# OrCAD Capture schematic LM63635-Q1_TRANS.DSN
size D; title: LM63635-Q1 3.5-V to 36-V, 3.25-A, Automotive Step-down; note: Datasheet: SNVSBK9C      EVM: SNVU617; note: Step-Down Converter.
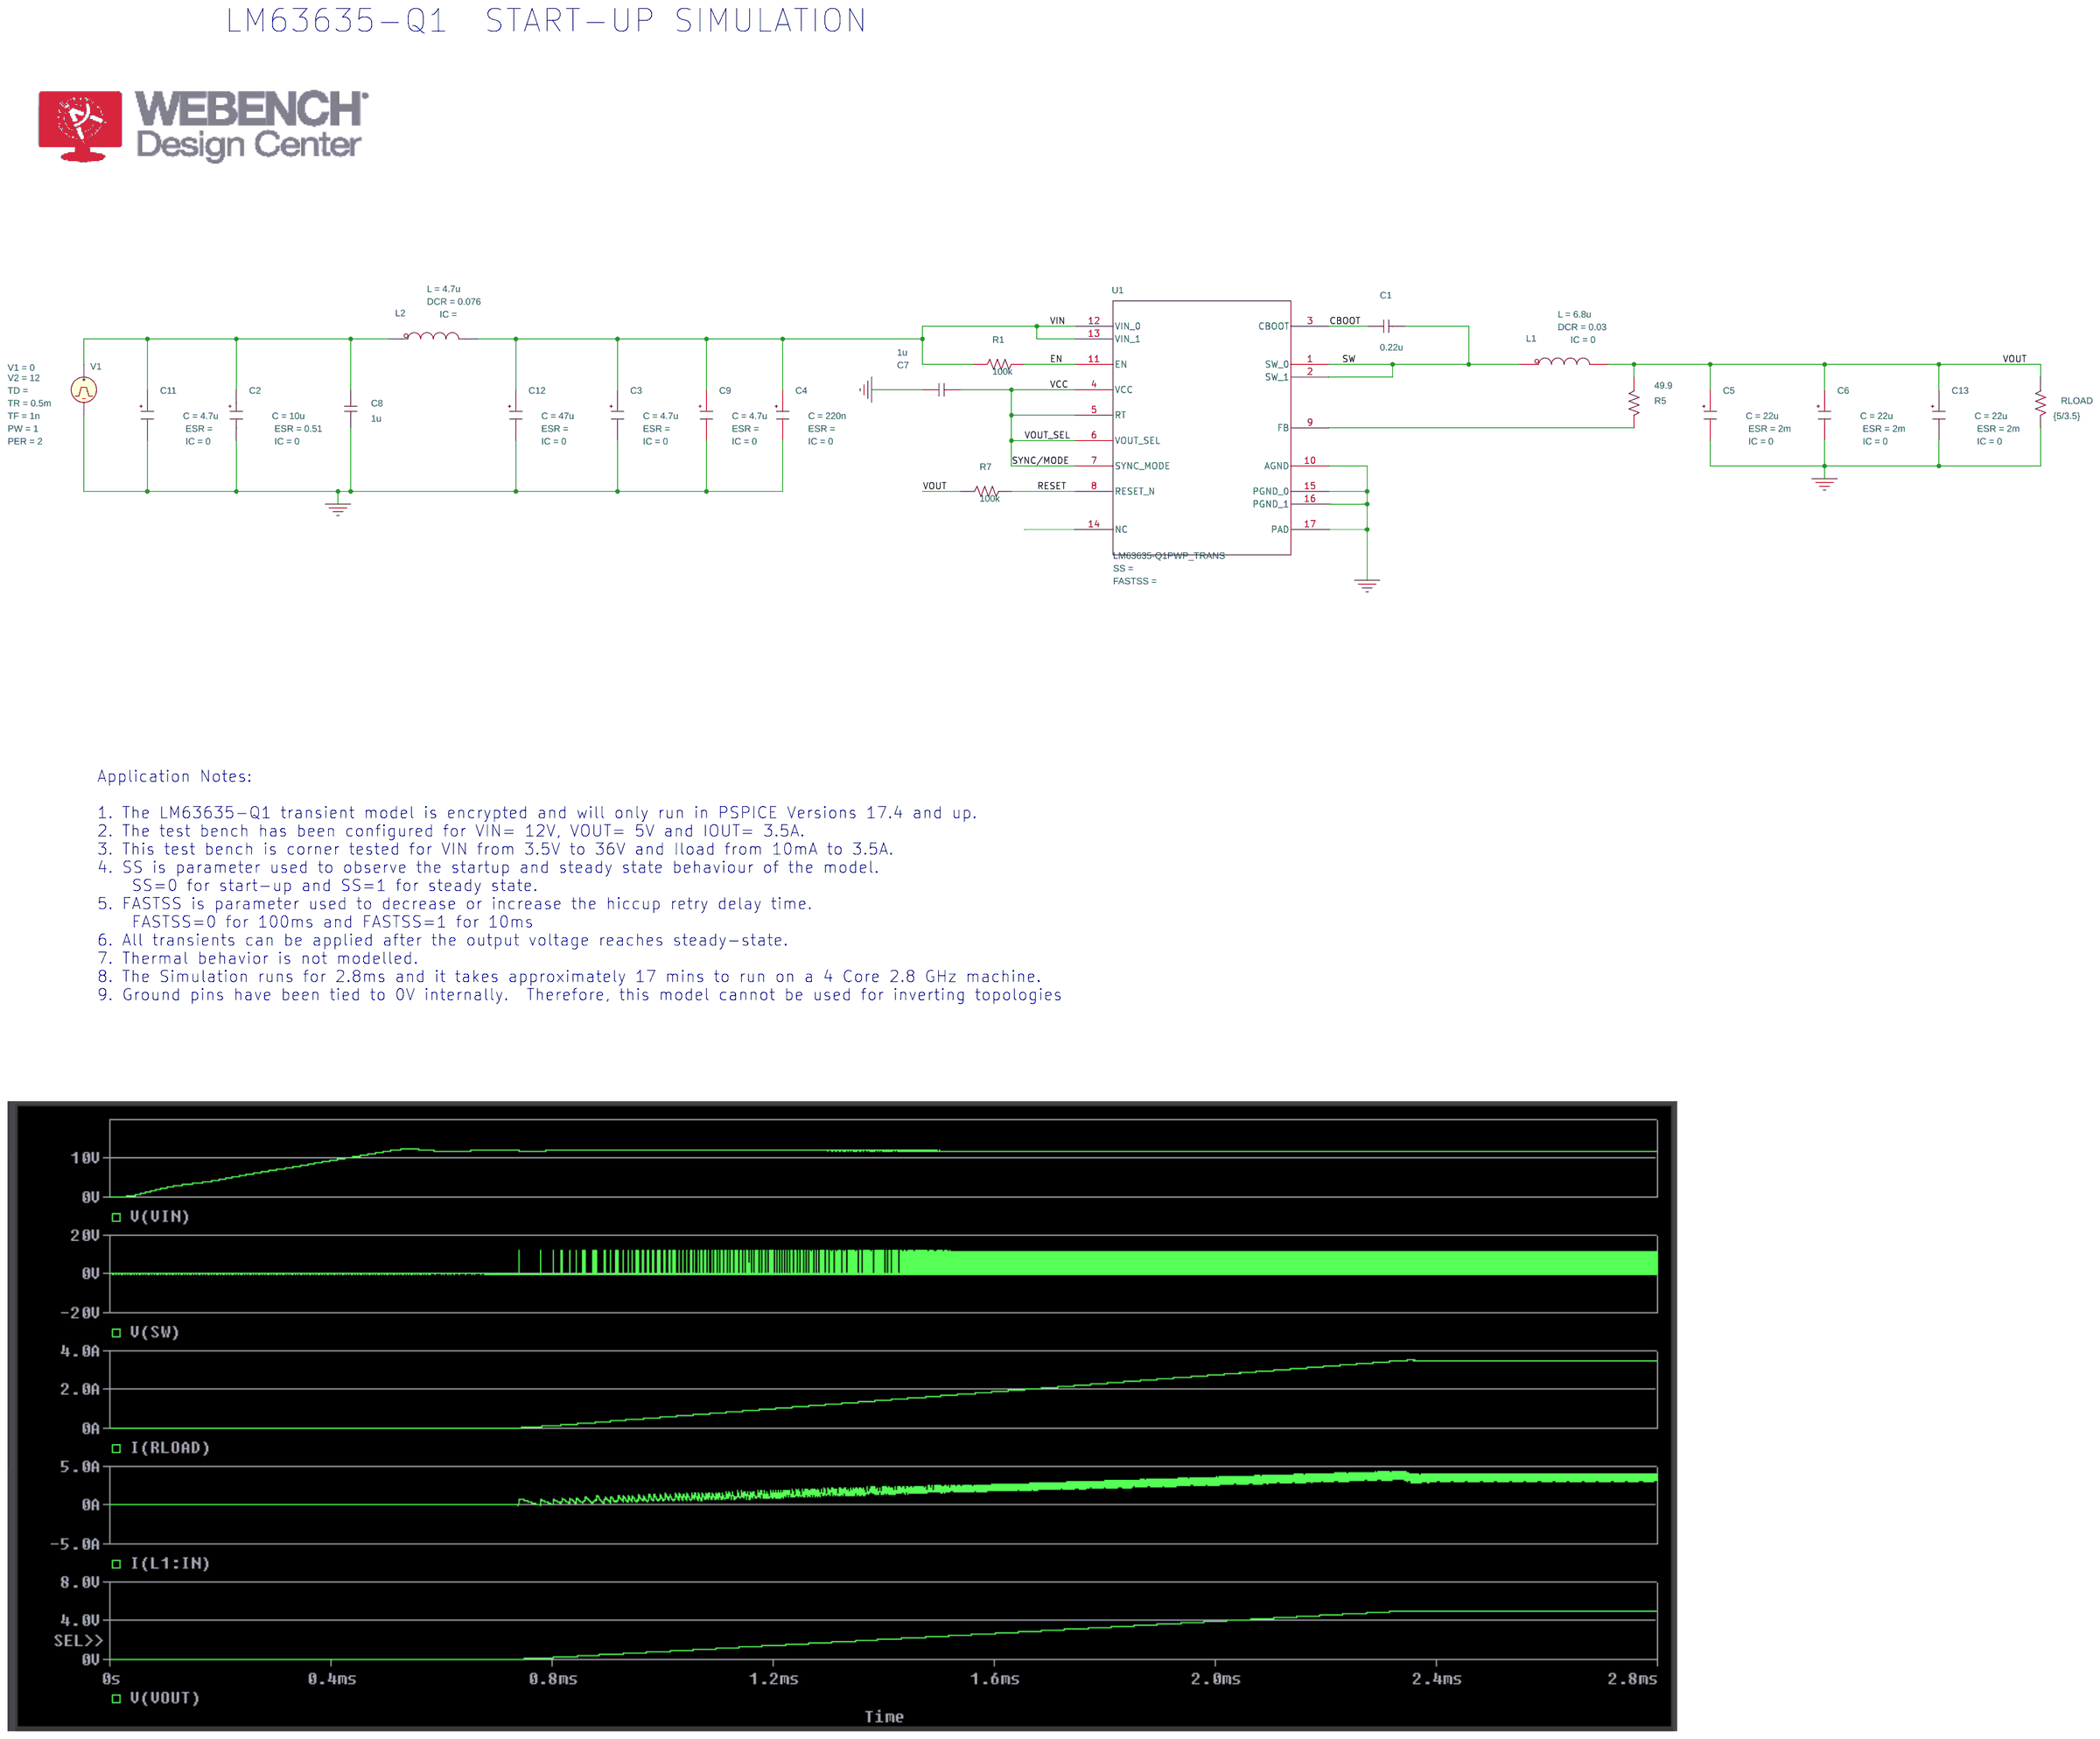
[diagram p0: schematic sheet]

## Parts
C1  0.22u  [RAD/CK05]
C2  CESR
C3  CESR
C4  CESR
C5  CESR
C6  CESR
C7  1u  [RAD/CK05]
C8  1u  [RAD/CK05]
C9  CESR
C11  CESR
C12  CESR
C13  CESR
L1  LDCR
L2  LDCR
R1  100k  [AX/RC05]
R5  49.9  [AX/RC05]
R7  100k  [AX/RC05]
RLOAD  {5/3.5}  [AX/RC05]
U1  LM63635-Q1PWP_TRANS  [PWP0016K_N]
V1  VPULSE

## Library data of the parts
C1 C7 C8 = C: IC: 0
C2 = CESR_0: C: 10u; ESR: 0.51; IC: 0; PSpiceTemplate: X^@REFDES %IN %OUT @MODEL PARAMS:  ?C|C=@C||C=100u|  ?ESR|ESR=@ESR||ESR=0.01| ?X|X=@X||X=2|  ?IC|IC=@IC||IC=2|; X: 1
C3 C9 = CESR_0: C: 4.7u; IC: 0; PSpiceTemplate: X^@REFDES %IN %OUT @MODEL PARAMS:  ?C|C=@C||C=100u|  ?ESR|ESR=@ESR||ESR=0.01| ?X|X=@X||X=2|  ?IC|IC=@IC||IC=2|; X: 2
C4 = CESR_0: C: 220n; IC: 0; PSpiceTemplate: X^@REFDES %IN %OUT @MODEL PARAMS:  ?C|C=@C||C=100u|  ?ESR|ESR=@ESR||ESR=0.01| ?X|X=@X||X=2|  ?IC|IC=@IC||IC=2|; X: 2
C5 = CESR_0: C: 22u; ESR: 2m; IC: 0; PSpiceTemplate: X^@REFDES %IN %OUT @MODEL PARAMS:  ?C|C=@C||C=100u|  ?ESR|ESR=@ESR||ESR=0.01| ?X|X=@X||X=2|  ?IC|IC=@IC||IC=2|; X: 1
C6 C13 = CESR_0: C: 22u; ESR: 2m; IC: 0; PSpiceTemplate: X^@REFDES %IN %OUT @MODEL PARAMS:  ?C|C=@C||C=100u|  ?ESR|ESR=@ESR||ESR=0.01| ?X|X=@X||X=2|  ?IC|IC=@IC||IC=2|; X: 2
C11 = CESR_0: C: 4.7u; IC: 0; PSpiceTemplate: X^@REFDES %IN %OUT @MODEL PARAMS:  ?C|C=@C||C=100u|  ?ESR|ESR=@ESR||ESR=0.01| ?X|X=@X||X=2|  ?IC|IC=@IC||IC=2|; X: 1
C12 = CESR_0: C: 47u; IC: 0; PSpiceTemplate: X^@REFDES %IN %OUT @MODEL PARAMS:  ?C|C=@C||C=100u|  ?ESR|ESR=@ESR||ESR=0.01| ?X|X=@X||X=2|  ?IC|IC=@IC||IC=2|; X: 2
L1 = LDCR_0: DCR: 0.03; IC: 0; L: 6.8u; PSpiceTemplate: X^@REFDES %IN %OUT @MODEL PARAMS:  ?L|L=@L||L=1u|  ?DCR|DCR=@DCR||DCR=0.01| ?IC|IC=@IC||IC=0|
L2 = LDCR_0: DCR: 0.076; L: 4.7u; PSpiceTemplate: X^@REFDES %IN %OUT @MODEL PARAMS:  ?L|L=@L||L=1u|  ?DCR|DCR=@DCR||DCR=0.01| ?IC|IC=@IC||IC=0|
R1 R5 R7 RLOAD = R
U1 = LM63635-Q1PWP_TRANS
V1 = VPULSE: PER: 2; PW: 1; TF: 1n; TR: 0.5m; V1: 0; V2: 12

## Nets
VIN: C3.1(IN) C4.1(IN) C9.1(IN) C12.1(IN) L2.3(OUT) R1.1 U1.12(VIN_0) U1.13(VIN_1)
0: C2.2(OUT) C3.2(OUT) C4.2(OUT) C5.2(OUT) C6.2(OUT) C7.1 C8.1 C9.2(OUT) C11.2(OUT) C12.2(OUT) C13.2(OUT) RLOAD.2 U1.10(AGND) U1.15(PGND_0) U1.16(PGND_1) U1.17(PAD) V1.2(-)
CBOOT: C1.1 U1.3(CBOOT)
EN: R1.2 U1.11(EN)
RESET: R7.2 U1.8(RESET_N)
SW: C1.2 L1.1(IN) U1.1(SW_0) U1.2(SW_1)
SYNC/MODE: C7.2 U1.4(VCC) U1.5(RT) U1.6(VOUT_SEL) U1.7(SYNC_MODE)
VOUT: C5.1(IN) C6.1(IN) C13.1(IN) L1.3(OUT) R5.1 R7.1 RLOAD.1
N00993: C2.1(IN) C8.2 C11.1(IN) L2.1(IN) V1.1(+)
N04548: R5.2 U1.9(FB)

Not connected (* = marked no-connect by the designer): U1 14(NC)

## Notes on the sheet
- LM63635-Q1  START-UP SIMULATION
- Application Notes:
  1. The LM63635-Q1 transient model is encrypted and will only run in PSPICE Versions 17.4 and up.
  2. The test bench has been configured for VIN= 12V, VOUT= 5V and IOUT= 3.5A.
  3. This test bench is corner tested for VIN from 3.5V to 36V and Iload from 10mA to 3.5A.
  4. SS is parameter used to observe the startup and steady state behaviour of the model.
      SS=0 for start-up and SS=1 for steady state.
  5. FASTSS is parameter used to decrease or increase the hiccup retry delay time.
      FASTSS=0 for 100ms and FASTSS=1 for 10ms
  6. All transients can be applied after the output voltage reaches steady-state.
  7. Thermal behavior is not modelled.
  8. The Simulation runs for 2.8ms and it takes approximately 17 mins to run on a 4 Core 2.8 GHz machine.
  9. Ground pins have been tied to 0V internally.  Therefore, this model cannot be used for inverting topologies
